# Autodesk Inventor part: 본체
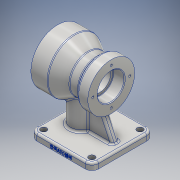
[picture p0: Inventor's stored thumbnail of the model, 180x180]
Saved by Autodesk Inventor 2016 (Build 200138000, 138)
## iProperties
Created: 2019-01
Part Number: 본체
Material: 알루미늄 6061
Document SubType Name: Modeling
Designer: USER
Density: 2.7 g/cm^3
Appearance: 알루미늄 - 평지
Mass: 898.787 g
Surface Area: 605.063 cm^2
Volume: 332.884 cm^3
Author: USER
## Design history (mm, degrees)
sketch "스케치1"
  geometry: L1 (0, 0)-(-80, 0); L2 (0, 26)-(-19, 26); L3 (-20, 25)-(-20, 16); L4 (-20, 16)-(-63, 16); L5 (-63, 16)-(-63, 19.4); L6 (-63.6, 20)-(-80, 20); L7 (-80, 20)-(-80, 35); L8 (0, 26)-(0, 40); L9 (0, 40)-(-25, 40); L10 (-80, 35)-(-65, 35); L11 (-45.785, 28)-(-59.126, 28); L12 (-25, 40)-(-45.785, 28); L13 (-65, 35)-(-59.126, 28); A1 r 1 centre (-19, 25) between (-19, 26) and (-20, 25); A2 r 0.6 centre (-63.6, 19.4) between (-63, 19.4) and (-63.6, 20); 4 further points
  constraints: 26 end point, 6 perpendicular, 4 horizontal, 4 point on circle, 4 point on line, 4 tangent, 2 centre point, 2 midpoint, 2 vertical alignment, 1 vertical
  dimensions: "d0" = 80 distance of L1.start L1.end; "d1" = 25 distance of L8.end L9.end; "d2" = 80 diameter of L9 L1; "d3" = 52 diameter of L2 L1; "d4" = 32 diameter of L4 L1; "d5" = 40 diameter of L6 L1; "d6" = 15 distance of L7.end L10.end; "d7" = 70 diameter of L10 L1; "d8" = 20 distance of L2.start point (-20, 26); "d9" = 17 distance of point (-63, 20) L6.end; "d10" = 56 diameter of L11 L1; "d11" = 30 deg angle of L12 L11; "d12" = 50 deg angle of L13 L11; "d60" = 1 radius of A1; "d61" = 0.6 radius of A2
revolve "회전1" sketch "스케치1" stored, may be unused: angle "d13" = 90 deg
node "작업 평면1"
sketch "스케치2"
  geometry: L1 (5, 46)-(97, 46); L2 (97, 46)-(97, -46); L3 (97, -46)-(5, -46); L4 (5, -46)-(5, 46); L5 (5, 46)-(97, -46); L6 (97, 46)-(5, -46); L7 (0, 40)-(0, -40) reference; 5 further points
  constraints: 12 end point, 6 midpoint, 2 parallel, 1 horizontal, 1 horizontal alignment, 1 perpendicular
  dimensions: "d15" = 92 distance of L1.start L1.end; "d16" = 92 distance of L1.end L2.end; "d67" = 5 distance between parallel lines of L4 L7
extrude "돌출1" join sketch "스케치2" distance "d17" = 10; taper "d18" = 0 deg
sketch "스케치3"
  geometry: C1 r 16 at (35, 0); 1 further point
  constraints: 1 centre point, 1 horizontal alignment
  dimensions: "d19" = 35 distance of C1.centre point (0, 0); "d20" = 32 diameter of C1
extrude "돌출2" join sketch "스케치3" stored distance "d21" = 10; taper "d22" = 0 deg
sketch "스케치4"
  geometry: L1 (-87, -70)-(-70.679, -35); L2 (-97, -80)-(-97, -70) reference; L3 (-97, -70)-(-5, -70) reference; L4 (-80, -35)-(-65, -35) reference; 1 further point
  constraints: 2 end point, 2 point on line
  dimensions: "d23" = 10 distance from line of L2 L1.start; "d24" = 25 deg angle of L1 L2
feature "리브1" sketch "스케치4" dims "d25" = 1, "d26" = 10, "d27" = 0, "d28" = 0, "d29" = 1, "d30" = 1
fillet "모깎기1" dims "d31" = 10
sketch "스케치5"
  geometry: C1 r 4.5 at (15, 36); C2 r 4.5 at (87, 36); A1 r 10 centre (15, 36) between (15, 46) and (5, 36) reference; A2 r 10 centre (87, 36) between (97, 36) and (87, 46) reference; 1 further point
  constraints: 2 centre point, 1 coincident, 1 concentric
  dimensions: "d32" = 9 diameter of C1; "d33" = 9 diameter of C2
extrude "돌출3" cut sketch "스케치5" distance "d34" = 10; taper "d35" = 0 deg
sketch "스케치6" dims "d36" = 66
  geometry: L1 (0, 0)-(33, 0); 5 further points
  constraints: 2 coincident, 2 end point, 1 horizontal, 1 horizontal alignment, 7 other
  dimensions: "d39" = 360 deg dimension on point (0, 0) L1.end (derived)
hole "구멍1" sketch "스케치6" at (33, 0), (0, -33), (0, 33), (-33, 0) diameter "d41" = 3.242; stored, may be unused: countersink angle "d45" = 90 deg, drill point angle "d47" = 118 deg; dims "d42" = 9, "d43" = 4, "d44" = 2, "d46" = 11
sketch "스케치7" dims "d48" = 55
  geometry: L1 (0, 0)-(-27.5, 0); 5 further points
  constraints: 2 coincident, 2 end point, 1 horizontal, 1 horizontal alignment, 7 other
  dimensions: "d51" = 360 deg dimension on point (0, 0) L1.end (derived)
hole "구멍2" sketch "스케치7" at (-27.5, 0), (0, -27.5), (27.5, 0), (0, 27.5) diameter "d53" = 3.242; stored, may be unused: countersink angle "d57" = 90 deg, drill point angle "d59" = 118 deg; dims "d54" = 9, "d55" = 4, "d56" = 2, "d58" = 11
chamfer "모따기1" distance "d62" = 1; stored, may be unused: second distance "d63" = 2, angle "d64" = 45 deg
fillet "모깎기2" dims "d65" = 3
fillet "모깎기3" dims "d66" = 3
sketch "스케치8"
  geometry: L1 (72, 0)-(0, 0) reference; L2 (-10, 7)-(-10, 0) reference; 2 further points
  constraints: 1 other
  dimensions: "d68" = 4 distance from line of L1 point (36, 4); "d69" = 46 distance from line of L2 point (36, 4)
feature "엠보싱1" sketch "스케치8" dims "d0" = 80, "d1" = 25, "d2" = 80, "d3" = 52, "d4" = 32, "d5" = 40, "d6" = 15, "d7" = 70, "d8" = 20, "d9" = 17, "d10" = 56, "d11" = 30 deg, "d12" = 50 deg, "d15" = 92, "d16" = 92, "d60" = 1, "d61" = 0.6, "d67" = 5, "d70" = 0.5, "d71" = 0
node "솔리드1"
mirror "대칭1"
